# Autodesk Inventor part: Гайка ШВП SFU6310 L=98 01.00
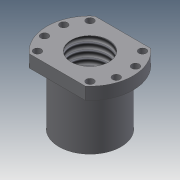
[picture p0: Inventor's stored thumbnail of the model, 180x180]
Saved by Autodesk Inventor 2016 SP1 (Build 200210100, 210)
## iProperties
Company: Проектная группа
Created: 2017-08
Part Number: Гайка ШВП SFU6310 L=98 01.00
Checked By: Сидоров ИА
Engr Approved By: Баев БГ
Material: Типовые
Document SubType Name: Modeling
Mfg Approved By: Босов АА
Designer: t1
Engineer: Иванов НИ
Authority: Петров ПП
Density: 1 g/cm^3
Appearance: По умолчанию
Mass: 453.286 g
Surface Area: 662.734 cm^2
Volume: 453.286 cm^3
Author: t1
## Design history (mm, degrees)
sketch "Эскиз2" dims "d25" = 108
  geometry: L1 (40.62, 47.5)-(-40.62, 47.5); L2 (-40.62, -47.5)-(40.62, -47.5); L3 (40.62, 47.5)-(-40.62, -47.5); L4 (-40.62, 47.5)-(40.62, -47.5); L5 (-50.588, 0)-(55.18, 0); L6 (0, 44.104)-(0, -52.475); L7 (-48.361, 12.958)-(0, 0); A1 r 62.5 centre (0, 0) between (40.62, -47.5) and (40.62, 47.5); A2 r 62.5 centre (0, 0) between (-40.62, 47.5) and (-40.62, -47.5); 3 further points
  constraints: 14 end point, 4 point on circle, 3 coincident, 2 centre point, 2 horizontal, 2 midpoint, 1 parallel, 1 point on line, 1 vertical, 3 other
  dimensions: "d24" = 95 distance between parallel lines of L1 L2; "d36" = 62.5 radius of A2; "d37" = 15 deg angle of L5 L7
extrude "Выдавливание1" new body sketch "Эскиз2" distance "d11" = 18; taper "d12" = 0 deg
sketch "Эскиз3"
  geometry: C1 r 62.5 at (0, 0) reference; C2 r 45 at (0, 0)
  constraints: 1 centre point, 1 coincident
  dimensions: "d13" = 90 diameter of C2
extrude "Выдавливание2" join sketch "Эскиз3" distance "d14" = 80; taper "d15" = 0 deg
hole "Отверстие1" sketch "Эскиз2" diameter "d16" = 55; stored, may be unused: countersink angle "d20" = 90 deg, drill point angle "d22" = 118 deg; dims "d17" = 130, "d18" = 4, "d19" = 2, "d21" = 190
hole "Отверстие3" sketch "Эскиз2" diameter "d38" = 11; stored, may be unused: countersink angle "d42" = 90 deg, drill point angle "d44" = 118 deg; dims "d39" = 6, "d40" = 4, "d41" = 2, "d43" = 8
pattern_circular "Круговой массив2" dims angle "d46" = 360 deg
node "Твердое тело2"
other parameters: "d10" = 42
